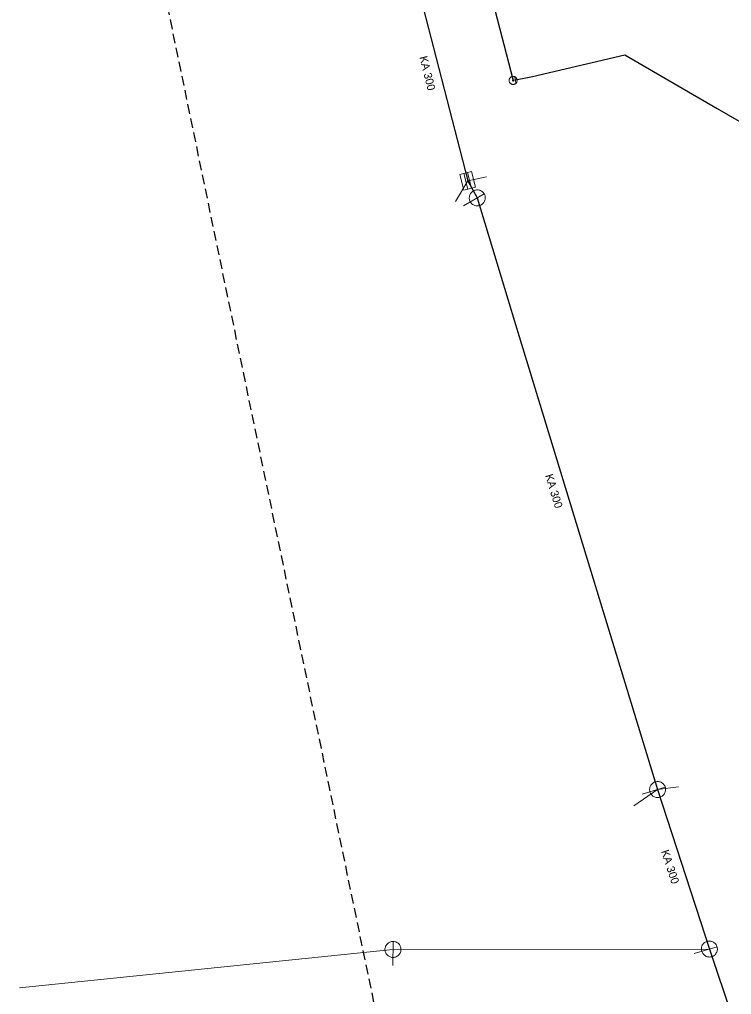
# Model space of a CAD drawing. Extents: x -807203 to -805207, y -993656 to -992505.
# Drawn here: x -807203.2 to -807114.1, y -993090.4 to -992968.6 of the extents above; entities that cross this region are included whole.
import ezdxf

# ---------------------------------------------------------------- set-up
doc = ezdxf.new("R2010")
doc.units = 0
doc.header["$LTSCALE"] = 0.4
doc.linetypes.add('MEDIUM_DASHED', pattern=[4.5, 3, -1.5])
for name, color, linetype, lineweight in [('1', 7, 'Continuous', 13), ('11', 7, 'Continuous', 13), ('14', 7, 'Continuous', 25), ('17', 7, 'Continuous', 25), ('22', 7, 'Continuous', 13), ('34', 7, 'Continuous', 13), ('47', 7, 'Continuous', 13), ('63', 7, 'MEDIUM_DASHED', 25)]:
    doc.layers.add(name, color=color, linetype=linetype, lineweight=lineweight)

msp = doc.modelspace()

# ---------------------------------------------------------------- linework, layer by layer
at = {"layer": '11'}
for p, q in [((-807144.787, -992988.266), (-807147.12, -992988.77)), ((-807148.649, -992991.355), (-807147.12, -992988.77)), ((-807126.336, -993066.878), (-807123.37, -993064.829)), ((-807120.757, -993064.475), (-807123.37, -993064.829))]:
    msp.add_line(p, q, dxfattribs=at)
msp.add_lwpolyline([(-807203.16, -993089.6), (-807156.462, -993084.81), (-807116.899, -993084.76)], dxfattribs=at)
at = {"layer": '14'}
for p, q in [((-807153.859, -992962.66), (-807147.12, -992988.77)), ((-807147.12, -992988.77), (-807145.92, -992990.899)), ((-807123.37, -993064.829), (-807116.899, -993084.76)), ((-807116.899, -993084.76), (-807110.309, -993104.32))]:
    msp.add_line(p, q, dxfattribs=at)
at = {"layer": '14', "lineweight": 13}
msp.add_line((-807141.147, -992976.164), (-807141.44, -992976.222), dxfattribs=at)
at = {"layer": '14'}
msp.add_lwpolyline([(-807145.92, -992990.899), (-807141.122, -993006.737), (-807123.37, -993064.829)], dxfattribs=at)
at = {"layer": '17'}
for points in [[(-807176.339, -992807.832), (-807185.25, -992823.421), (-807176.901, -992849.778), (-807171.201, -992869.482), (-807166.822, -992884.952), (-807166.197, -992887.01), (-807162.951, -992898.684), (-807161.445, -992904.008), (-807154.07, -992930.199), (-807151.949, -992937.442), (-807146.899, -992955.136), (-807141.44, -992976.222)], [(-807141.147, -992976.164), (-807139.035, -992975.721), (-807127.458, -992973.026), (-807115.923, -992979.745), (-807095.09, -992991.726), (-807073.804, -993003.811), (-807049.627, -993008.616), (-807049.088, -993013.868), (-807049.022, -993023.329), (-807048.875, -993026.192), (-807050.069, -993026.403)]]:
    msp.add_lwpolyline(points, dxfattribs=at)
at = {"layer": '22'}
for p, q in [((-807147.608, -992987.851), (-807147.108, -992989.788)), ((-807147.124, -992987.726), (-807146.624, -992989.663)), ((-807147.662, -992991.88), (-807145.049, -992990.408)), ((-807125.284, -993065.408), (-807122.413, -993064.539)), ((-807156.483, -993086.81), (-807156.451, -993083.81)), ((-807118.816, -993085.329), (-807115.94, -993084.475))]:
    msp.add_line(p, q, dxfattribs=at)
for points in [[(-807146.64, -992987.602), (-807146.14, -992989.538), (-807147.592, -992989.913), (-807148.092, -992987.976)], [(-807145.429, -992991.77), (-807145.337, -992991.711), (-807145.252, -992991.643), (-807145.174, -992991.564), (-807145.106, -992991.48), (-807145.047, -992991.387), (-807144.999, -992991.289), (-807144.962, -992991.185), (-807144.937, -992991.079), (-807144.922, -992990.97), (-807144.921, -992990.861), (-807144.93, -992990.752), (-807144.953, -992990.645), (-807144.987, -992990.541), (-807145.031, -992990.441), (-807145.087, -992990.346), (-807145.152, -992990.259), (-807145.227, -992990.178), (-807145.309, -992990.106), (-807145.4, -992990.045), (-807145.496, -992989.993), (-807145.598, -992989.952), (-807145.703, -992989.923), (-807145.812, -992989.905), (-807145.921, -992989.899), (-807146.03, -992989.905), (-807146.138, -992989.923), (-807146.244, -992989.953), (-807146.345, -992989.994), (-807146.442, -992990.046), (-807146.532, -992990.108), (-807146.615, -992990.179), (-807146.689, -992990.26), (-807146.754, -992990.347), (-807146.81, -992990.442), (-807146.854, -992990.542), (-807146.887, -992990.646), (-807146.909, -992990.754), (-807146.919, -992990.863), (-807146.918, -992990.972), (-807146.903, -992991.081), (-807146.878, -992991.187), (-807146.84, -992991.29), (-807146.792, -992991.389), (-807146.733, -992991.481), (-807146.664, -992991.566), (-807146.587, -992991.643), (-807146.502, -992991.712), (-807146.409, -992991.771), (-807146.311, -992991.819), (-807146.208, -992991.856), (-807146.101, -992991.882), (-807145.993, -992991.896), (-807145.883, -992991.899), (-807145.775, -992991.888), (-807145.667, -992991.866), (-807145.563, -992991.833), (-807145.463, -992991.788)], [(-807123.08, -993065.786), (-807122.977, -993065.748), (-807122.879, -993065.7), (-807122.787, -993065.64), (-807122.702, -993065.573), (-807122.624, -993065.495), (-807122.556, -993065.41), (-807122.497, -993065.317), (-807122.449, -993065.219), (-807122.412, -993065.115), (-807122.386, -993065.009), (-807122.372, -993064.901), (-807122.371, -993064.79), (-807122.381, -993064.682), (-807122.403, -993064.574), (-807122.437, -993064.47), (-807122.482, -993064.37), (-807122.537, -993064.275), (-807122.602, -993064.187), (-807122.677, -993064.108), (-807122.759, -993064.037), (-807122.85, -993063.974), (-807122.946, -993063.923), (-807123.049, -993063.882), (-807123.154, -993063.852), (-807123.262, -993063.835), (-807123.371, -993063.829), (-807123.481, -993063.835), (-807123.588, -993063.853), (-807123.694, -993063.883), (-807123.795, -993063.924), (-807123.892, -993063.975), (-807123.981, -993064.038), (-807124.064, -993064.109), (-807124.139, -993064.189), (-807124.204, -993064.278), (-807124.26, -993064.372), (-807124.304, -993064.472), (-807124.338, -993064.576), (-807124.36, -993064.683), (-807124.369, -993064.793), (-807124.368, -993064.902), (-807124.353, -993065.011), (-807124.327, -993065.118), (-807124.29, -993065.22), (-807124.241, -993065.318), (-807124.183, -993065.41), (-807124.114, -993065.496), (-807124.037, -993065.574), (-807123.951, -993065.642), (-807123.859, -993065.701), (-807123.761, -993065.749), (-807123.658, -993065.786), (-807123.552, -993065.813), (-807123.443, -993065.826), (-807123.334, -993065.828), (-807123.224, -993065.818), (-807123.117, -993065.796)], [(-807155.462, -993084.821), (-807155.466, -993084.712), (-807155.483, -993084.604), (-807155.512, -993084.497), (-807155.551, -993084.396), (-807155.602, -993084.298), (-807155.663, -993084.208), (-807155.734, -993084.124), (-807155.813, -993084.049), (-807155.9, -993083.982), (-807155.994, -993083.926), (-807156.093, -993083.88), (-807156.198, -993083.846), (-807156.305, -993083.823), (-807156.414, -993083.811), (-807156.524, -993083.812), (-807156.632, -993083.825), (-807156.739, -993083.849), (-807156.843, -993083.885), (-807156.941, -993083.933), (-807157.034, -993083.99), (-807157.12, -993084.058), (-807157.198, -993084.134), (-807157.268, -993084.219), (-807157.328, -993084.311), (-807157.377, -993084.408), (-807157.415, -993084.511), (-807157.442, -993084.617), (-807157.458, -993084.725), (-807157.461, -993084.835), (-807157.452, -993084.944), (-807157.432, -993085.051), (-807157.399, -993085.156), (-807157.356, -993085.256), (-807157.302, -993085.352), (-807157.237, -993085.441), (-807157.164, -993085.521), (-807157.082, -993085.594), (-807156.993, -993085.657), (-807156.897, -993085.71), (-807156.796, -993085.752), (-807156.691, -993085.784), (-807156.583, -993085.803), (-807156.473, -993085.81), (-807156.364, -993085.805), (-807156.256, -993085.788), (-807156.151, -993085.76), (-807156.048, -993085.721), (-807155.951, -993085.67), (-807155.86, -993085.609), (-807155.776, -993085.538), (-807155.7, -993085.459), (-807155.635, -993085.372), (-807155.578, -993085.279), (-807155.532, -993085.179), (-807155.497, -993085.075), (-807155.474, -993084.968), (-807155.463, -993084.859)], [(-807116.614, -993085.718), (-807116.512, -993085.682), (-807116.413, -993085.634), (-807116.32, -993085.575), (-807116.235, -993085.508), (-807116.157, -993085.43), (-807116.088, -993085.345), (-807116.029, -993085.252), (-807115.981, -993085.155), (-807115.942, -993085.052), (-807115.916, -993084.946), (-807115.902, -993084.837), (-807115.9, -993084.727), (-807115.909, -993084.618), (-807115.931, -993084.511), (-807115.964, -993084.406), (-807116.008, -993084.306), (-807116.063, -993084.211), (-807116.127, -993084.123), (-807116.202, -993084.043), (-807116.284, -993083.971), (-807116.375, -993083.908), (-807116.47, -993083.856), (-807116.572, -993083.815), (-807116.677, -993083.784), (-807116.785, -993083.766), (-807116.894, -993083.76), (-807117.004, -993083.765), (-807117.112, -993083.783), (-807117.218, -993083.812), (-807117.319, -993083.853), (-807117.416, -993083.903), (-807117.506, -993083.966), (-807117.589, -993084.036), (-807117.665, -993084.116), (-807117.73, -993084.204), (-807117.786, -993084.298), (-807117.831, -993084.398), (-807117.865, -993084.502), (-807117.888, -993084.609), (-807117.898, -993084.718), (-807117.897, -993084.827), (-807117.883, -993084.936), (-807117.858, -993085.043), (-807117.821, -993085.146), (-807117.773, -993085.244), (-807117.716, -993085.337), (-807117.647, -993085.423), (-807117.57, -993085.501), (-807117.485, -993085.57), (-807117.393, -993085.629), (-807117.295, -993085.678), (-807117.192, -993085.716), (-807117.086, -993085.742), (-807116.978, -993085.756), (-807116.868, -993085.759), (-807116.759, -993085.75), (-807116.651, -993085.728)]]:
    msp.add_lwpolyline(points, close=True, dxfattribs=at)
at = {"layer": '34'}
msp.add_line((-807141.25, -992975.674), (-807141.044, -992976.653), dxfattribs=at)
at = {"layer": '47'}
for points in [[(-807141.291, -992976.699), (-807141.242, -992976.681), (-807141.195, -992976.657), (-807141.151, -992976.629), (-807141.11, -992976.598), (-807141.072, -992976.561), (-807141.039, -992976.52), (-807141.01, -992976.476), (-807140.986, -992976.43), (-807140.966, -992976.382), (-807140.952, -992976.331), (-807140.943, -992976.279), (-807140.94, -992976.227), (-807140.942, -992976.175), (-807140.95, -992976.123), (-807140.962, -992976.073), (-807140.98, -992976.024), (-807141.004, -992975.977), (-807141.032, -992975.932), (-807141.063, -992975.892), (-807141.1, -992975.854), (-807141.141, -992975.821), (-807141.185, -992975.791), (-807141.231, -992975.767), (-807141.279, -992975.747), (-807141.33, -992975.734), (-807141.382, -992975.725), (-807141.434, -992975.721), (-807141.486, -992975.724), (-807141.538, -992975.732), (-807141.588, -992975.744), (-807141.637, -992975.762), (-807141.684, -992975.786), (-807141.729, -992975.813), (-807141.769, -992975.845), (-807141.807, -992975.882), (-807141.841, -992975.922), (-807141.87, -992975.966), (-807141.894, -992976.012), (-807141.914, -992976.061), (-807141.927, -992976.112), (-807141.936, -992976.164), (-807141.94, -992976.215), (-807141.937, -992976.268), (-807141.929, -992976.32), (-807141.917, -992976.37), (-807141.899, -992976.419), (-807141.875, -992976.466), (-807141.848, -992976.51), (-807141.816, -992976.551), (-807141.779, -992976.589), (-807141.739, -992976.623), (-807141.695, -992976.651), (-807141.649, -992976.675), (-807141.6, -992976.695), (-807141.549, -992976.709), (-807141.497, -992976.718), (-807141.446, -992976.721), (-807141.393, -992976.719), (-807141.341, -992976.711)], [(-807141.415, -992976.3), (-807141.407, -992976.297), (-807141.399, -992976.293), (-807141.392, -992976.289), (-807141.386, -992976.283), (-807141.379, -992976.277), (-807141.374, -992976.27), (-807141.369, -992976.263), (-807141.365, -992976.256), (-807141.362, -992976.248), (-807141.36, -992976.24), (-807141.358, -992976.231), (-807141.358, -992976.222), (-807141.358, -992976.214), (-807141.359, -992976.206), (-807141.361, -992976.197), (-807141.364, -992976.189), (-807141.368, -992976.181), (-807141.372, -992976.174), (-807141.378, -992976.168), (-807141.384, -992976.161), (-807141.391, -992976.156), (-807141.398, -992976.151), (-807141.405, -992976.147), (-807141.414, -992976.143), (-807141.421, -992976.142), (-807141.43, -992976.14), (-807141.439, -992976.14), (-807141.447, -992976.14), (-807141.455, -992976.141), (-807141.464, -992976.143), (-807141.472, -992976.146), (-807141.48, -992976.15), (-807141.487, -992976.154), (-807141.493, -992976.16), (-807141.5, -992976.166), (-807141.505, -992976.172), (-807141.51, -992976.18), (-807141.514, -992976.187), (-807141.518, -992976.196), (-807141.519, -992976.203), (-807141.521, -992976.212), (-807141.521, -992976.221), (-807141.521, -992976.229), (-807141.52, -992976.237), (-807141.518, -992976.246), (-807141.515, -992976.254), (-807141.511, -992976.262), (-807141.507, -992976.269), (-807141.501, -992976.275), (-807141.495, -992976.282), (-807141.489, -992976.287), (-807141.481, -992976.292), (-807141.474, -992976.296), (-807141.466, -992976.299), (-807141.458, -992976.301), (-807141.449, -992976.303), (-807141.44, -992976.303), (-807141.432, -992976.303), (-807141.424, -992976.302)]]:
    msp.add_lwpolyline(points, close=True, dxfattribs=at)
at = {"layer": '63'}
msp.add_lwpolyline([(-807189.02, -992945.815), (-806576.348, -992585.749), (-806576.348, -992585.749), (-805244.939, -992598.309), (-805244.939, -992598.309), (-805207.257, -992947.211), (-805207.257, -992947.211), (-805210.049, -993545.926), (-805210.049, -993545.926), (-805797.599, -993596.168), (-805797.599, -993596.168), (-807062.019, -993558.487), (-807062.019, -993558.487)], close=True, dxfattribs=at)

# ---------------------------------------------------------------- texts
at = {"layer": '1'}
for rotation, p in [(284, (-807153.161, -992973.306)), (287, (-807137.449, -993025.583)), (288, (-807122.948, -993072.553))]:
    msp.add_text('KA 300', height=1, rotation=rotation, dxfattribs=at).set_placement(p)

doc.saveas('drawing.dxf')
